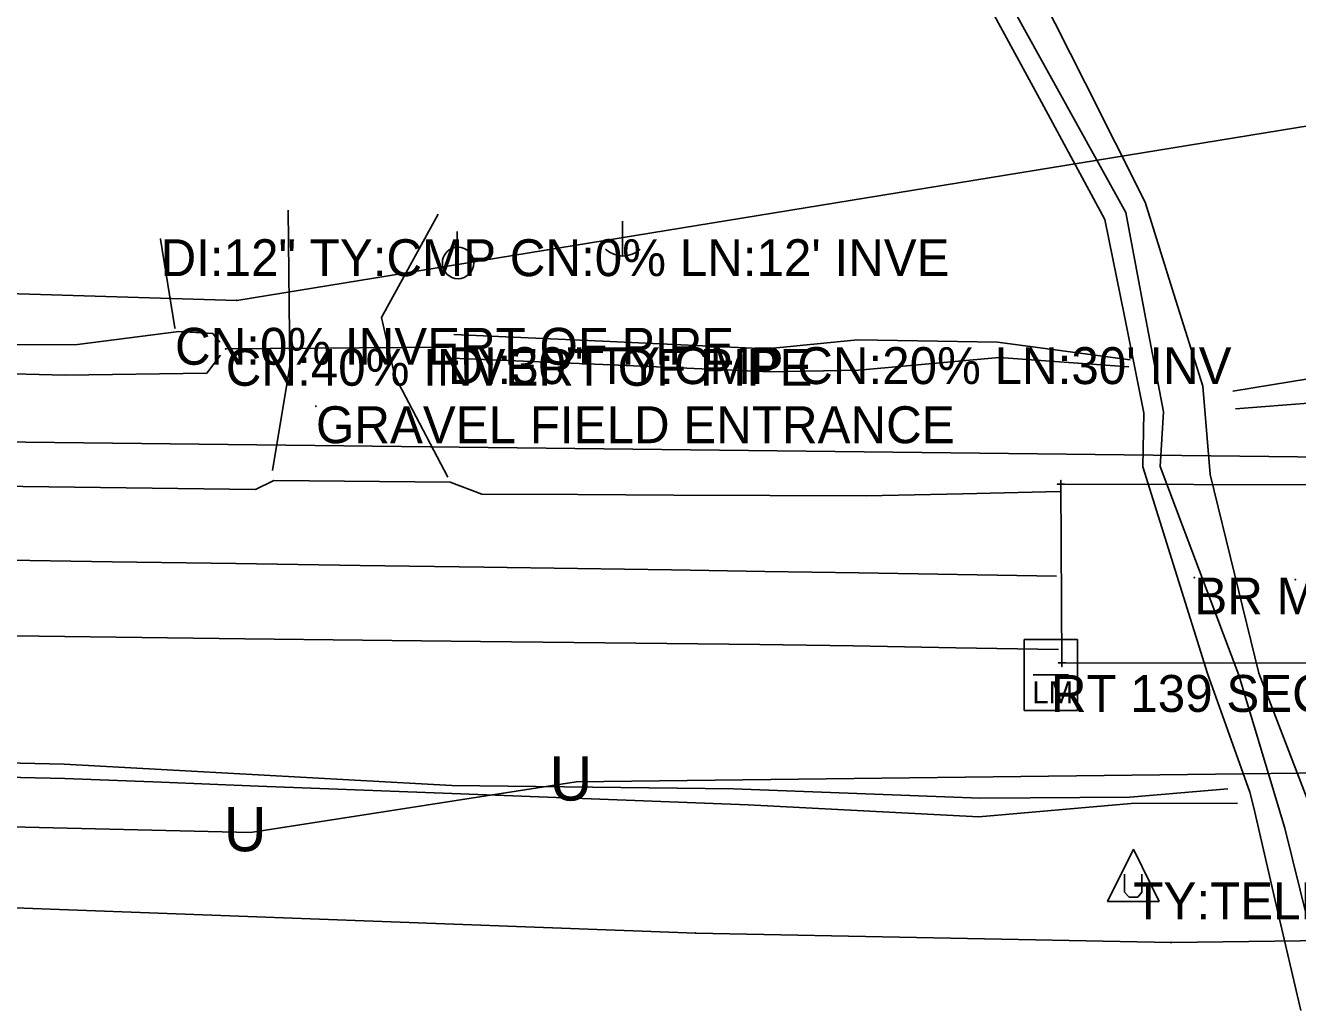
# Model space of a CAD drawing. Extents: x 1810987 to 1814397, y 533216 to 533930.
# Drawn here: x 1812364.1 to 1812536.5, y 533500.2 to 533633.6 of the extents above; entities that cross this region are included whole.
import ezdxf

# ---------------------------------------------------------------- set-up
doc = ezdxf.new("R2010")
doc.units = 0
for name, color, linetype in [('Default', 7, 'Continuous'), ('S_BASELINE', 7, 'Continuous'), ('S_BRIDGE', 7, 'Continuous'), ('S_DITCHLINE', 7, 'Continuous'), ('S_DRG_PT_SYM', 7, 'Continuous'), ('S_DRIVEWAY', 7, 'Continuous'), ('S_EDGE_PAVEMENT', 7, 'Continuous'), ('S_GAS_UTILITIES', 7, 'Continuous'), ('S_LOG_MILE', 7, 'Continuous'), ('S_LOG_MILE_ANNOT', 7, 'Continuous'), ('S_MSC_PT_SYM', 7, 'Continuous'), ('S_PAVEMENT_CROWN', 7, 'Continuous'), ('S_SIDE_DRAIN', 7, 'Continuous'), ('S_SIDE_DRAIN_ANNOT', 7, 'Continuous'), ('S_STR_PT_SYM', 7, 'Continuous'), ('S_STREAM', 7, 'Continuous'), ('S_SURVEY_TEXT_ANNOT', 7, 'Continuous'), ('S_UNDERGROUND_CABLE', 7, 'Continuous'), ('S_UTILITY_POLE', 7, 'Continuous'), ('S_UTILITY_POLE_ANNOT', 7, 'Continuous'), ('S_UTL_PT_SYM', 7, 'Continuous'), ('S_WATER_UTILITIES', 7, 'Continuous')]:
    doc.layers.add(name, color=color, linetype=linetype)

msp = doc.modelspace()

# ---------------------------------------------------------------- linework, layer by layer
at = {"layer": 'S_BASELINE'}
msp.add_line((1811772.1, 533584), (1812583.73, 533574.67), dxfattribs=at)
at = {"layer": 'S_BRIDGE'}
for p, q in [((1812550.77, 533571.41), (1812504.44, 533571.5)), ((1812504.44, 533571.5), (1812504.58, 533547.28)), ((1812504.58, 533547.28), (1812550.61, 533547.27))]:
    msp.add_line(p, q, dxfattribs=at)
at = {"layer": 'S_DITCHLINE'}
for points in [[(1812349.02, 533590.31), (1812371.12, 533590.43), (1812384.87, 533592.18), (1812389.48, 533591.91), (1812390.45, 533590.72)], [(1812422.13, 533591.79), (1812443.32, 533590.81), (1812464.51, 533589.83), (1812476.88, 533591.07), (1812495.84, 533590.75), (1812513.84, 533588.33)], [(1812527.72, 533584.11), (1812540.72, 533586.23), (1812553.71, 533588.36), (1812572.17, 533589.51), (1812580.52, 533586.92)], [(1812348.18, 533586.83), (1812369.45, 533586.27), (1812388.69, 533586.55), (1812390.54, 533588.96)], [(1812421.87, 533588.57), (1812443.44, 533587.66), (1812465.01, 533586.74), (1812477.02, 533586.96), (1812496.07, 533588.64), (1812513.63, 533587.4)], [(1812528.11, 533581.69), (1812552.45, 533583.6), (1812572.02, 533585.33), (1812580.46, 533585.45)], [(1812249.51, 533536.36), (1812263.77, 533536.45), (1812278.02, 533536.54), (1812299.7, 533535.58), (1812321.39, 533534.62), (1812345.37, 533534.09), (1812369.35, 533533.56), (1812382.48, 533532.84), (1812395.61, 533532.11), (1812408.75, 533531.39), (1812421.88, 533530.66), (1812440.96, 533530.44), (1812460.05, 533530.22), (1812476.76, 533529.6), (1812493.47, 533528.98), (1812513.76, 533529.11), (1812527.05, 533530.22)], [(1812249.37, 533534.84), (1812263.56, 533534.61), (1812277.74, 533534.37), (1812299.51, 533533.55), (1812321.29, 533532.73), (1812345.35, 533532.17), (1812369.42, 533531.61), (1812382.53, 533531.11), (1812395.64, 533530.6), (1812408.76, 533530.1), (1812421.87, 533529.59), (1812441.95, 533528.84), (1812462.03, 533528.08), (1812477.67, 533527.26), (1812493.32, 533526.43), (1812513.96, 533528.26), (1812528.38, 533528.28)]]:
    msp.add_lwpolyline(points, dxfattribs=at)
at = {"layer": 'S_DRG_PT_SYM'}
for points in [[(1812382.4, 533604.68), (1812382.4, 533604.73), (1812382.4, 533604.68), (1812382.35, 533604.68), (1812382.4, 533604.68), (1812382.4, 533604.63), (1812382.4, 533604.68), (1812382.45, 533604.68)], [(1812384.35, 533592.68), (1812384.35, 533592.73), (1812384.35, 533592.68), (1812384.3, 533592.68), (1812384.35, 533592.68), (1812384.35, 533592.63), (1812384.35, 533592.68), (1812384.4, 533592.68)], [(1812391.24, 533589.83), (1812391.24, 533589.88), (1812391.24, 533589.83), (1812391.19, 533589.83), (1812391.24, 533589.83), (1812391.24, 533589.78), (1812391.24, 533589.83), (1812391.29, 533589.83)], [(1812421.36, 533590.06), (1812421.36, 533590.11), (1812421.36, 533590.06), (1812421.31, 533590.06), (1812421.36, 533590.06), (1812421.36, 533590.01), (1812421.36, 533590.06), (1812421.41, 533590.06)]]:
    msp.add_lwpolyline(points, dxfattribs=at)
at = {"layer": 'S_DRIVEWAY'}
for points in [[(1812399.69, 533608.6), (1812399.91, 533587.49), (1812397.57, 533573.34)], [(1812420.02, 533608.07), (1812412.33, 533594.07), (1812414.15, 533586.13), (1812421.35, 533572.45)]]:
    msp.add_lwpolyline(points, dxfattribs=at)
at = {"layer": 'S_EDGE_PAVEMENT'}
for points in [[(1812207.03, 533573.2), (1812231.17, 533572.98), (1812255.31, 533572.75), (1812277.54, 533572.45), (1812299.77, 533572.16), (1812314.87, 533571.93), (1812329.98, 533571.69), (1812345.08, 533571.46), (1812360.19, 533571.23), (1812377.73, 533571.01), (1812395.28, 533570.79), (1812397.77, 533572.01), (1812421.67, 533571.79), (1812425.93, 533570.14), (1812438.95, 533570.08), (1812451.98, 533570.02), (1812465, 533569.96), (1812478.02, 533569.9), (1812491.16, 533570.2), (1812504.29, 533570.49)], [(1812206.49, 533553.06), (1812231.12, 533552.69), (1812255.75, 533552.32), (1812269.03, 533552.17), (1812282.31, 533552.02), (1812295.59, 533551.87), (1812308.87, 533551.73), (1812321.39, 533551.54), (1812333.91, 533551.36), (1812346.43, 533551.18), (1812358.94, 533551), (1812376.37, 533550.78), (1812393.8, 533550.56), (1812409.78, 533550.38), (1812425.76, 533550.2), (1812438.39, 533550.05), (1812451.02, 533549.9), (1812463.64, 533549.76), (1812476.27, 533549.61), (1812490.18, 533549.35), (1812504.1, 533549.09)]]:
    msp.add_lwpolyline(points, dxfattribs=at)
at = {"layer": 'S_GAS_UTILITIES'}
for p, q in [((1812392.73, 533596.39), (1812577.11, 533626.45)), ((1812014.71, 533607.84), (1812392.73, 533596.39))]:
    msp.add_line(p, q, dxfattribs=at)
at = {"layer": 'S_LOG_MILE'}
for p, q in [((1812503.07, 533550.45), (1812506.67, 533550.45)), ((1812500.67, 533545.65), (1812505.47, 533545.65)), ((1812503.07, 533540.85), (1812499.47, 533540.85))]:
    msp.add_line(p, q, dxfattribs=at)
msp.add_lwpolyline([(1812506.67, 533550.45), (1812499.47, 533550.45), (1812499.47, 533540.85), (1812506.67, 533540.85)], close=True, dxfattribs=at)
at = {"layer": 'S_MSC_PT_SYM'}
for points in [[(1812403.46, 533582.05), (1812403.46, 533582.1), (1812403.46, 533582.05), (1812403.41, 533582.05), (1812403.46, 533582.05), (1812403.46, 533582), (1812403.46, 533582.05), (1812403.51, 533582.05)], [(1812522.52, 533558.85), (1812522.52, 533558.9), (1812522.52, 533558.85), (1812522.47, 533558.85), (1812522.52, 533558.85), (1812522.52, 533558.8), (1812522.52, 533558.85), (1812522.57, 533558.85)], [(1812536.21, 533558.57), (1812536.21, 533558.62), (1812536.21, 533558.57), (1812536.16, 533558.57), (1812536.21, 533558.57), (1812536.21, 533558.52), (1812536.21, 533558.57), (1812536.26, 533558.57)]]:
    msp.add_lwpolyline(points, dxfattribs=at)
at = {"layer": 'S_PAVEMENT_CROWN'}
msp.add_lwpolyline([(1812207.24, 533563.08), (1812231.51, 533562.92), (1812255.77, 533562.76), (1812269.21, 533562.54), (1812282.64, 533562.32), (1812296.08, 533562.09), (1812309.52, 533561.87), (1812334.26, 533561.55), (1812359.01, 533561.23), (1812375.82, 533560.99), (1812392.62, 533560.74), (1812409.43, 533560.49), (1812426.23, 533560.25), (1812438.93, 533560.06), (1812451.63, 533559.88), (1812464.32, 533559.69), (1812477.02, 533559.51), (1812490.43, 533559.28), (1812503.83, 533559.05)], dxfattribs=at)
at = {"layer": 'S_SIDE_DRAIN'}
for p, q in [((1812382.4, 533604.68), (1812384.35, 533592.68)), ((1812421.36, 533590.06), (1812391.24, 533589.83))]:
    msp.add_line(p, q, dxfattribs=at)
at = {"layer": 'S_STR_PT_SYM'}
for points in [[(1812504.44, 533571.5), (1812504.44, 533572), (1812504.44, 533571.5), (1812503.94, 533571.5), (1812504.44, 533571.5), (1812504.44, 533571), (1812504.44, 533571.5), (1812504.94, 533571.5)], [(1812504.58, 533547.28), (1812504.58, 533547.78), (1812504.58, 533547.28), (1812504.08, 533547.28), (1812504.58, 533547.28), (1812504.58, 533546.78), (1812504.58, 533547.28), (1812505.08, 533547.28)]]:
    msp.add_lwpolyline(points, dxfattribs=at)
at = {"layer": 'S_STREAM'}
for points in [[(1812499.6, 533642), (1812507.72, 533625.86), (1812515.85, 533609.72), (1812519.76, 533597.26), (1812523.68, 533584.8)], [(1812495.53, 533640.3), (1812504.39, 533624.3), (1812513.24, 533608.29), (1812515.78, 533594.79), (1812518.33, 533581.3), (1812517.9, 533573.89), (1812523.23, 533559.76), (1812528.55, 533545.64), (1812534.8, 533524.89), (1812537.9, 533512.3)], [(1812493.16, 533639.14), (1812501.78, 533623.25), (1812510.39, 533607.36), (1812513.03, 533594.27), (1812515.67, 533581.18), (1812515.53, 533573.86), (1812519.91, 533559.86), (1812524.28, 533545.87), (1812530.03, 533529.78), (1812530.57, 533527.66), (1812533.76, 533513.93), (1812536.94, 533500.19)], [(1812524.65, 533572.81), (1812523.68, 533584.8)], [(1812524.65, 533572.81), (1812527.95, 533559.35), (1812531.25, 533545.9), (1812538.27, 533527.71)]]:
    msp.add_lwpolyline(points, dxfattribs=at)
at = {"layer": 'S_UNDERGROUND_CABLE'}
for p, q in [((1812438.75, 533531.19), (1812578.83, 533532.86)), ((1812394.6, 533524.32), (1812438.75, 533531.19)), ((1812310.14, 533526.27), (1812394.6, 533524.32)), ((1812514.25, 533522.07), (1812510.73, 533514.98)), ((1812514.25, 533522.07), (1812517.74, 533514.98)), ((1812513.05, 533516.22), (1812513.05, 533518.66)), ((1812515.42, 533518.66), (1812515.42, 533516.22)), ((1812513.67, 533515.56), (1812513.05, 533516.22)), ((1812514.87, 533515.56), (1812513.67, 533515.56)), ((1812515.42, 533516.22), (1812514.87, 533515.56)), ((1812510.73, 533514.98), (1812517.74, 533514.98))]:
    msp.add_line(p, q, dxfattribs=at)
at = {"layer": 'S_UTILITY_POLE'}
for p, q in [((1812445.01, 533607.12), (1812445.01, 533602.39)), ((1812422.59, 533603.61), (1812422.59, 533605.72))]:
    msp.add_line(p, q, dxfattribs=at)
msp.add_circle((1812422.72, 533601.47), 2.13, dxfattribs=at)
msp.add_arc((1812445.07, 533605.82), 3.41, 226.3972, 313.6028, dxfattribs=at)
at = {"layer": 'S_UTL_PT_SYM'}
for points in [[(1812392.73, 533596.39), (1812392.73, 533596.44), (1812392.73, 533596.39), (1812392.68, 533596.39), (1812392.73, 533596.39), (1812392.73, 533596.34), (1812392.73, 533596.39), (1812392.78, 533596.39)], [(1812454.93, 533510.69), (1812454.93, 533510.74), (1812454.93, 533510.69), (1812454.88, 533510.69), (1812454.93, 533510.69), (1812454.93, 533510.64), (1812454.93, 533510.69), (1812454.98, 533510.69)], [(1812519.36, 533509.41), (1812519.36, 533509.46), (1812519.36, 533509.41), (1812519.31, 533509.41), (1812519.36, 533509.41), (1812519.36, 533509.36), (1812519.36, 533509.41), (1812519.41, 533509.41)]]:
    msp.add_lwpolyline(points, dxfattribs=at)
at = {"layer": 'S_WATER_UTILITIES'}
for p, q in [((1812218.82, 533519.45), (1812454.93, 533510.69)), ((1812454.93, 533510.69), (1812519.36, 533509.41)), ((1812519.36, 533509.41), (1812586.98, 533510.34))]:
    msp.add_line(p, q, dxfattribs=at)

# ---------------------------------------------------------------- texts
at = {"layer": 'Default'}
for p in [(1812435.12, 533528.64), (1812390.97, 533521.77)]:
    msp.add_text('U', height=6, dxfattribs=at).set_placement(p)
at = {"layer": 'S_LOG_MILE'}
msp.add_text('LM', height=3, dxfattribs=at).set_placement((1812500.53, 533541.81))
at = {"layer": 'S_LOG_MILE_ANNOT'}
msp.add_text('RT 139 SEC 0 LM 2.54', height=5, dxfattribs=at).set_placement((1812503.07, 533540.65))
at = {"layer": 'S_SIDE_DRAIN_ANNOT'}
for s, p in [('DI:12" TY:CMP CN:0% LN:12\' INVE', (1812382.4, 533599.68)), ('CN:0% INVERT OF PIPE', (1812384.35, 533587.68)), ('CN:40% INVERT OF PIPE', (1812391.24, 533584.83)), ('DI:30" TY:CMP CN:20% LN:30\' INV', (1812421.36, 533585.06))]:
    msp.add_text(s, height=5, dxfattribs=at).set_placement(p)
at = {"layer": 'S_SURVEY_TEXT_ANNOT'}
for s, p in [('GRAVEL FIELD ENTRANCE', (1812403.46, 533577.05)), ('BR M1983 WOOD DECK/PIERS', (1812522.52, 533553.85))]:
    msp.add_text(s, height=5, dxfattribs=at).set_placement(p)
at = {"layer": 'S_UTILITY_POLE_ANNOT'}
msp.add_text('TY:TELEPHONE CONTEL', height=5, dxfattribs=at).set_placement((1812514.25, 533512.54))

doc.saveas('drawing.dxf')
